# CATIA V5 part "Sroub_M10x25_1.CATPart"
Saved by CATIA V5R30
Part number: Sroub_M10x25_1
Definition: E 1200_10x25_2
Nomenclature: E 1200_10x25_2
Source: Unknown
Description: PART--DESC
Bounding box of the stored display mesh (mm): x 147 to 163, y 82 to 98, z -219 to -184
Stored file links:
  E:\Bakalarka\Model\Forma_v7\Sroub_M10x25_1.CATPart
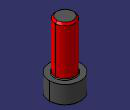
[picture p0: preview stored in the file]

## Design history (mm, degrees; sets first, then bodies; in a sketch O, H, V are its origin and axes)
Body1 "MANIFOLD_SOLID_BREP #4002" (main body)
  Solid1: solid without history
